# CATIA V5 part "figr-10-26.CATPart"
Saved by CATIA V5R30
Part number: Part1
Bounding box of the stored display mesh (mm): x -65.919 to 25.581, y -200.404 to 0.194, z 0 to 71.635
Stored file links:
  D:\PROJECTS\CATIA V56R 2020\Resources\Parts File\c10_catia_v5_6r2020_prt\figr-10-26.CATPart
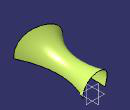
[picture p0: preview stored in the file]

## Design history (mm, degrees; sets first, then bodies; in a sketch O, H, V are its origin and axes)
Set1
  Sketch1 on xy-plane, origin (0, 0, 0), H (1, 0, 0), V (0, 1, 0)
    spline S1 through (-36.6295, 0) (-39.5961, -76.7629) (-56.6868, -154.7631) (-92.5015, -194.2587)
    point P1 (-36.6295, 0)
    coincidence: P1 H
  Sketch2 on xy-plane, origin (0, 0, 0), H (1, 0, 0), V (0, 1, 0)
    spline S1 through (25.5807, 0) (5.5021, -50.6307) (25.5807, -200.404)
    point P1 (25.5807, 0)
    coincidence: P1 H
  Sketch3 on zx-plane, origin (0, 0, 0), H (-1, 0, 0), V (0, 0, 1)
    spline S1 through (-25.5807, 0) (16.4189, 47.2175) (28.9802, 46.33) (36.6295, 0)
    reference projected point E1 (36.6295, 0) from vertex of Sketch1
    reference projected point E2 (-25.5807, 0) from vertex of Sketch2
    point P1 (-25.5807, 0)
    point P2 (36.6295, 0)
    coincidence: P1 H, P2 H, E1 P2, P1 E2
  Sweep1: type Unspec, Profile Sketch3, Guide (Sketch1; Sketch2), FittingPoints (vertex of Sketch1; vertex of Sketch2)
Body1 (main body)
